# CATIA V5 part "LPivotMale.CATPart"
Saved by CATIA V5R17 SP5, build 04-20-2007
Part number: PivotMale
Publications: "Centre", "Axe", "Facteur d'échelle"
Bounding box of the stored display mesh (mm): x -20 to 20, y -5 to 5, z 0 to 0
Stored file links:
  E:\Mes documents\03_Ressources pédagogiques\01_Catia\Buggy Dassault\SchemaCinematiqueFinal\LPivotMale.CATPart
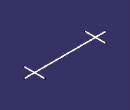
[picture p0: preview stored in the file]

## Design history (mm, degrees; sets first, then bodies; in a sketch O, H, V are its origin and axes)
External parameters (linked from other documents)
  `External.Facteur d'échelle` = 2
AxisSystem1: origin (0, 0, 0), X (1, 0, 0), Y (0, 1, 0), Z (0, 0, 1)
Body1 "PivotMale" (main body)
  Point1 "Centre": (0, 0, 0), in AxisSystem1
  Line1 "Axe": type PtPt, FirstPoint {point type Coord, X -20 {= -10mm*`External.Facteur d'échelle`}, Y 0, Z 0, RefAxis AxisSystem1}, SecondPoint {point type Coord, X 20 {= 10mm*`External.Facteur d'échelle`}, Y 0, Z 0, RefAxis AxisSystem1}
  Line2: type PtPt, FirstPoint {point type Coord, X -15 {= -7.5mm*`External.Facteur d'échelle`}, Y -5 {= -2.5mm*`External.Facteur d'échelle`}, Z 0, RefAxis AxisSystem1}, SecondPoint {point type Coord, X -15 {= -7.5mm*`External.Facteur d'échelle`}, Y 5 {= 2.5mm*`External.Facteur d'échelle`}, Z 0, RefAxis AxisSystem1}
  Line3: type PtPt, FirstPoint {point type Coord, X 15 {= 7.5mm*`External.Facteur d'échelle`}, Y -5 {= -2.5mm*`External.Facteur d'échelle`}, Z 0, RefAxis AxisSystem1}, SecondPoint {point type Coord, X 15 {= 7.5mm*`External.Facteur d'échelle`}, Y 5 {= 2.5mm*`External.Facteur d'échelle`}, Z 0, RefAxis AxisSystem1}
